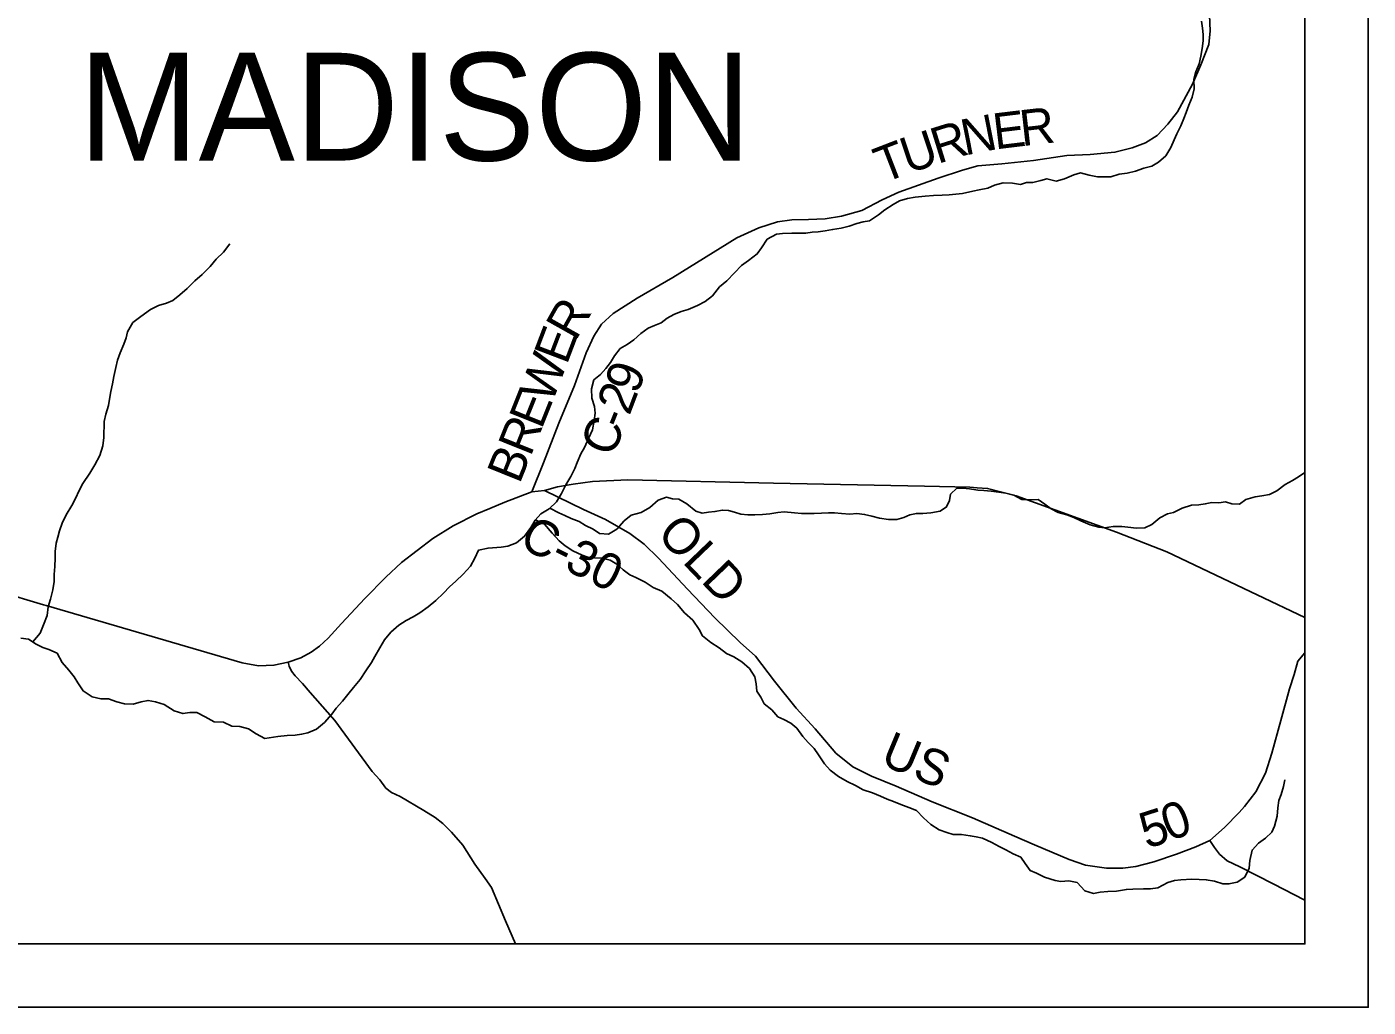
# Model space of a CAD drawing. Extents: x 0 to 34, y 0 to 22.
# Drawn here: x 28.295 to 30.417, y 14 to 15.55 of the extents above; entities that cross this region are included whole.
import ezdxf

# ---------------------------------------------------------------- set-up
doc = ezdxf.new("R2010")
doc.units = 0
for name, color, linetype in [('GM_X_County_Road', 7, 'Continuous'), ('GM_X_County_Road_Text', 7, 'Continuous'), ('GM_X_Minor_River', 7, 'Continuous'), ('GM_X_Township_Road', 7, 'Continuous'), ('GM_X_Township_Text', 7, 'Continuous'), ('GM_X_US_Route', 7, 'Continuous'), ('SH_Data', 7, 'Continuous')]:
    doc.layers.add(name, color=color, linetype=linetype)

msp = doc.modelspace()

# ---------------------------------------------------------------- linework, layer by layer
at = {"layer": 'GM_X_County_Road'}
for points in [[(29.0942, 14.815), (29.1127, 14.8606), (29.1368, 14.9236), (29.1618, 14.9831), (29.1801, 15.0347), (29.1922, 15.061), (29.2042, 15.08), (29.2229, 15.0971), (29.2605, 15.1211), (29.3173, 15.1536), (29.4185, 15.2164), (29.4533, 15.2326), (29.4824, 15.242), (29.5052, 15.2449), (29.5315, 15.2458), (29.5578, 15.2465), (29.584, 15.2509), (29.616, 15.2598), (29.648, 15.2766), (29.6743, 15.2889), (29.7369, 15.3107), (29.7752, 15.3234), (29.7993, 15.3307), (29.8373, 15.3338), (29.8873, 15.3389), (29.9402, 15.3468), (29.9772, 15.3484), (30.0161, 15.3519), (30.0437, 15.3589), (30.0646, 15.3668), (30.0829, 15.3785), (30.0997, 15.3962), (30.1152, 15.4161), (30.139, 15.4598), (30.1523, 15.4899), (30.1649, 15.5225), (30.1668, 15.5437), (30.1656, 15.5687)], [(29.1143, 14.8169), (29.1757, 14.7872), (29.2106, 14.771), (29.2491, 14.7492), (29.2719, 14.7321), (29.2944, 14.7099), (29.3403, 14.6612), (29.3834, 14.6156), (29.4234, 14.5765), (29.4479, 14.5549), (29.478, 14.5153), (29.5119, 14.4726), (29.5422, 14.4402), (29.5746, 14.4019), (29.6018, 14.3798), (29.6312, 14.3652), (29.6705, 14.3494), (29.7271, 14.3247), (29.7908, 14.2992), (29.8572, 14.2702), (29.8889, 14.2566), (29.944, 14.2335), (29.9699, 14.2243), (30.0028, 14.2199), (30.0285, 14.2199), (30.0491, 14.2224), (30.0779, 14.2297), (30.1133, 14.2421), (30.1443, 14.2538), (30.1664, 14.2635)], [(30.1664, 14.2635), (30.1893, 14.2842), (30.2124, 14.3079), (30.2209, 14.3174), (30.239, 14.3405), (30.2545, 14.37), (30.2643, 14.4016), (30.2786, 14.4532), (30.2925, 14.5032), (30.2995, 14.5263), (30.3052, 14.5471), (30.3167, 14.5601)], [(30.3167, 14.1692), (30.2666, 14.1951), (30.2138, 14.2219), (30.1936, 14.2315), (30.1817, 14.2419), (30.1734, 14.2523), (30.1664, 14.2635)]]:
    msp.add_lwpolyline(points, dxfattribs=at)
at = {"layer": 'GM_X_Minor_River'}
for points in [[(30.1409, 15.4671), (30.1439, 15.479), (30.1495, 15.4915), (30.1522, 15.504), (30.1541, 15.5158), (30.1556, 15.5283), (30.1555, 15.5382), (30.1548, 15.548), (30.1532, 15.559)], [(29.6656, 15.2691), (29.6754, 15.2752), (29.6883, 15.279), (29.7004, 15.2809), (29.716, 15.2825), (29.7292, 15.2836), (29.7432, 15.284), (29.7542, 15.2844), (29.7648, 15.2856), (29.775, 15.2867), (29.7913, 15.2902), (29.8016, 15.2925), (29.8152, 15.2951), (29.8258, 15.3001), (29.8394, 15.3035), (29.8542, 15.3028), (29.8667, 15.3009), (29.8765, 15.3039), (29.8864, 15.3043), (29.8989, 15.3074), (29.9087, 15.3101), (29.9231, 15.3063), (29.9364, 15.3101), (29.9511, 15.3162), (29.9617, 15.3192), (29.9754, 15.3158), (29.9887, 15.3132), (29.9993, 15.3128), (30.0095, 15.3132), (30.0227, 15.3174), (30.0356, 15.319), (30.0485, 15.322), (30.0617, 15.327), (30.0746, 15.33), (30.0852, 15.3361), (30.0969, 15.3463), (30.1045, 15.3596), (30.1098, 15.3714), (30.1143, 15.3809), (30.1204, 15.3938), (30.1253, 15.4055), (30.1287, 15.415), (30.1332, 15.4264), (30.1385, 15.4389), (30.1415, 15.4522), (30.1409, 15.4671)], [(28.6717, 14.4251), (28.6924, 14.4282), (28.7071, 14.4297), (28.72, 14.4301), (28.7299, 14.4316), (28.7401, 14.4336), (28.7533, 14.4396), (28.7662, 14.4503), (28.7776, 14.4632), (28.7847, 14.4727), (28.7946, 14.4841), (28.8029, 14.4947), (28.812, 14.5057), (28.8226, 14.5182), (28.8316, 14.5319), (28.8403, 14.5448), (28.846, 14.5547), (28.8536, 14.568), (28.8611, 14.5809), (28.8713, 14.593), (28.8838, 14.604), (28.8956, 14.6112), (28.9062, 14.6173), (28.9171, 14.6234), (28.93, 14.6333), (28.9421, 14.6432), (28.9542, 14.6546), (28.9637, 14.6648), (28.9739, 14.6736), (28.9856, 14.6846), (28.9973, 14.6975), (29.0041, 14.71), (29.0098, 14.7229), (29.025, 14.726), (29.0454, 14.7275), (29.056, 14.729), (29.07, 14.7344), (29.0825, 14.7446), (29.0927, 14.7583), (29.0995, 14.77), (29.1082, 14.7803), (29.1215, 14.7879), (29.1332, 14.7993), (29.1411, 14.8122), (29.1479, 14.8262), (29.1559, 14.8391), (29.1619, 14.8517), (29.1657, 14.8615), (29.1717, 14.8748), (29.1774, 14.8851), (29.1838, 14.8991), (29.1899, 14.9128), (29.1929, 14.9276), (29.194, 14.9393), (29.1932, 14.9499), (29.1891, 14.9632), (29.1887, 14.9776), (29.1921, 14.992), (29.2027, 15.0004), (29.211, 15.0099), (29.2185, 15.0194), (29.225, 15.03), (29.234, 15.0414), (29.2446, 15.0478), (29.2556, 15.0554), (29.2662, 15.0653), (29.2783, 15.0737), (29.2882, 15.0782), (29.2984, 15.0824), (29.3082, 15.0893), (29.3185, 15.0954), (29.3302, 15.0999), (29.3415, 15.1033), (29.3559, 15.1098), (29.3684, 15.1159), (29.3798, 15.125), (29.3911, 15.1391), (29.4025, 15.1486), (29.4146, 15.1615), (29.4259, 15.1729), (29.4365, 15.1808), (29.4505, 15.1911), (29.4573, 15.2006), (29.4664, 15.2143), (29.4808, 15.2222), (29.4906, 15.2234), (29.505, 15.2242), (29.5168, 15.2238), (29.5274, 15.2238), (29.5372, 15.2254), (29.5471, 15.2261), (29.5577, 15.2277), (29.5698, 15.2296), (29.5831, 15.2319), (29.5959, 15.2353), (29.6081, 15.2391), (29.6179, 15.2418), (29.6281, 15.2437), (29.6421, 15.2532), (29.6523, 15.2608), (29.6656, 15.2691)], [(28.3051, 14.5775), (28.3164, 14.5912), (28.3218, 14.6048), (28.3275, 14.6196), (28.329, 14.6329), (28.3328, 14.6454), (28.3366, 14.6598), (28.3389, 14.673), (28.3389, 14.684), (28.3397, 14.6969), (28.3401, 14.7102), (28.3405, 14.7204), (28.342, 14.7337), (28.3443, 14.7431), (28.347, 14.7534), (28.3515, 14.7655), (28.3576, 14.7787), (28.3667, 14.7935), (28.3724, 14.8045), (28.3781, 14.817), (28.3841, 14.828), (28.3951, 14.8446), (28.4031, 14.8575), (28.4111, 14.8723), (28.4156, 14.8878), (28.4175, 14.9007), (28.4176, 14.9264), (28.4206, 14.9378), (28.4248, 14.9514), (28.426, 14.9617), (28.4283, 14.9738), (28.4309, 14.9855), (28.4328, 14.9973), (28.4363, 15.0113), (28.4386, 15.0234), (28.4431, 15.0348), (28.4488, 15.0484), (28.4526, 15.0587), (28.4545, 15.0681), (28.4632, 15.0825), (28.4757, 15.0923), (28.4909, 15.1033), (28.5037, 15.1094), (28.5166, 15.1131), (28.5264, 15.1173), (28.5374, 15.1267), (28.5488, 15.1366), (28.5613, 15.1487), (28.5727, 15.1585), (28.5852, 15.1714), (28.595, 15.1831), (28.6064, 15.1937), (28.6166, 15.207)], [(30.2722, 14.8164), (30.2855, 14.8267), (30.2968, 14.8331), (30.3067, 14.8385), (30.3167, 14.8453)], [(29.1225, 14.7889), (29.1366, 14.7819), (29.1461, 14.7773), (29.1563, 14.7728), (29.1689, 14.7679), (29.1787, 14.7618), (29.1912, 14.7558), (29.2011, 14.749), (29.2151, 14.7482), (29.2283, 14.7558), (29.2401, 14.7691), (29.251, 14.7782), (29.2669, 14.782), (29.2809, 14.7904), (29.2938, 14.8018), (29.3071, 14.8064), (29.3165, 14.8041), (29.3264, 14.8034), (29.3393, 14.7962), (29.3533, 14.7844), (29.3635, 14.7814), (29.3734, 14.7826), (29.3836, 14.7837), (29.3954, 14.786), (29.4052, 14.7856), (29.4147, 14.783), (29.4245, 14.7796), (29.4359, 14.7785), (29.4469, 14.7785), (29.459, 14.7789), (29.4704, 14.7804), (29.4832, 14.782), (29.4931, 14.7835), (29.5094, 14.7816), (29.5207, 14.7805), (29.531, 14.7809), (29.5408, 14.7809), (29.5522, 14.7813), (29.5632, 14.7817), (29.5726, 14.7817), (29.5836, 14.7806), (29.5969, 14.7798), (29.6082, 14.7806), (29.6204, 14.7791), (29.6317, 14.7765), (29.6439, 14.7735), (29.6583, 14.7712), (29.6715, 14.7712), (29.6821, 14.7743), (29.692, 14.7785), (29.7022, 14.7807), (29.7124, 14.7808), (29.7249, 14.7815), (29.7397, 14.7846), (29.7499, 14.791), (29.7548, 14.8013), (29.7563, 14.8115), (29.7661, 14.8207), (29.7756, 14.8207), (29.7862, 14.8195), (29.7995, 14.8177), (29.809, 14.8169), (29.8203, 14.8158), (29.8328, 14.8143), (29.8438, 14.8128), (29.8563, 14.8098), (29.8688, 14.803), (29.8813, 14.8022), (29.8946, 14.8026), (29.9056, 14.7954), (29.9154, 14.7879), (29.9264, 14.7822), (29.9401, 14.7784), (29.9511, 14.7743), (29.9624, 14.769), (29.9768, 14.7629), (29.9905, 14.7588), (29.9999, 14.758), (30.0136, 14.7599), (30.0272, 14.76), (30.0367, 14.7592), (30.0503, 14.7573), (30.0636, 14.7581), (30.0746, 14.7634), (30.0874, 14.7737), (30.0992, 14.7802), (30.109, 14.7824), (30.1223, 14.7889), (30.1374, 14.7939), (30.1488, 14.7946), (30.159, 14.7958), (30.1696, 14.7981), (30.1806, 14.7977), (30.1908, 14.7992), (30.201, 14.7962), (30.2132, 14.7955), (30.2234, 14.8027), (30.2378, 14.8069), (30.2484, 14.8084), (30.2605, 14.8107), (30.2722, 14.8164)], [(29.0999, 14.7705), (29.1143, 14.764), (29.1264, 14.7496), (29.1374, 14.7375), (29.1469, 14.7295), (29.1591, 14.7216), (29.1735, 14.7148), (29.1829, 14.7114), (29.1932, 14.7103), (29.2049, 14.7099), (29.2182, 14.7069), (29.2284, 14.7005), (29.2383, 14.6914), (29.2493, 14.6838), (29.2587, 14.6796), (29.2731, 14.6721), (29.286, 14.6637), (29.2997, 14.6577), (29.3145, 14.6456), (29.3243, 14.6369), (29.3357, 14.6236), (29.3486, 14.6119), (29.3585, 14.5971), (29.3642, 14.5872), (29.3774, 14.5766), (29.3903, 14.5683), (29.4017, 14.5592), (29.4134, 14.5539), (29.4263, 14.546), (29.4385, 14.5354), (29.4468, 14.5225), (29.4487, 14.5111), (29.4499, 14.4998), (29.4563, 14.4903), (29.4613, 14.4797), (29.4734, 14.4702), (29.4833, 14.4592), (29.4927, 14.4547), (29.5037, 14.449), (29.5132, 14.4411), (29.5227, 14.4282), (29.531, 14.4183), (29.5405, 14.4089), (29.5473, 14.399), (29.5568, 14.385), (29.5659, 14.3748), (29.5788, 14.3649), (29.5925, 14.357), (29.6057, 14.3506), (29.6179, 14.3438), (29.6326, 14.3388), (29.6452, 14.3339), (29.6558, 14.329), (29.666, 14.3252), (29.6777, 14.3207), (29.6903, 14.3158), (29.7024, 14.3109), (29.7134, 14.2995), (29.7248, 14.2889), (29.738, 14.2806), (29.7502, 14.2761), (29.7604, 14.273), (29.7736, 14.2731), (29.7873, 14.2712), (29.7968, 14.2693), (29.8066, 14.267), (29.8214, 14.2602), (29.8331, 14.2542), (29.8438, 14.2489), (29.8555, 14.2425), (29.8673, 14.2372), (29.8741, 14.2273), (29.8821, 14.2159), (29.8919, 14.2118), (29.9048, 14.2054), (29.9215, 14.2001), (29.9309, 14.1989), (29.9434, 14.1997), (29.9563, 14.1971), (29.9685, 14.1842), (29.9821, 14.1797), (29.9931, 14.1816), (30.0052, 14.1827), (30.0188, 14.1835), (30.0344, 14.1862), (30.0446, 14.1866), (30.0613, 14.187), (30.0722, 14.187), (30.084, 14.1885), (30.0999, 14.1973), (30.1105, 14.2003), (30.1203, 14.2015), (30.1378, 14.2026), (30.1495, 14.2019), (30.1605, 14.2015), (30.1737, 14.1993), (30.187, 14.1948), (30.1965, 14.1948), (30.2094, 14.1978), (30.2215, 14.2054), (30.2283, 14.2198)], [(28.2862, 14.5833), (28.2979, 14.5821), (28.3104, 14.5742), (28.3206, 14.5688), (28.3304, 14.5654), (28.3432, 14.5597), (28.3512, 14.5453), (28.3617, 14.5328), (28.3704, 14.5225), (28.3761, 14.5131), (28.3844, 14.5002), (28.3987, 14.491)], [(28.3987, 14.491), (28.4123, 14.4876), (28.4248, 14.4876), (28.4377, 14.483), (28.4501, 14.4796), (28.4634, 14.4792), (28.4762, 14.483), (28.4872, 14.4852), (28.4989, 14.4829), (28.5129, 14.4784), (28.5284, 14.4685), (28.5424, 14.4643), (28.5534, 14.4662), (28.5643, 14.4662), (28.5776, 14.4593), (28.5919, 14.4513), (28.6063, 14.4506), (28.6199, 14.4445), (28.6324, 14.4441), (28.646, 14.4403), (28.6581, 14.4323), (28.6717, 14.4251)], [(30.2283, 14.2198), (30.2294, 14.232), (30.2332, 14.2483), (30.243, 14.2593), (30.2543, 14.2673), (30.2642, 14.2768), (30.2687, 14.2863), (30.2725, 14.3018), (30.274, 14.3151), (30.2755, 14.3268), (30.2789, 14.3363), (30.2827, 14.3492), (30.2849, 14.3595)]]:
    msp.add_lwpolyline(points, dxfattribs=at)
at = {"layer": 'GM_X_Township_Road'}
msp.add_lwpolyline([(29.068, 14.1), (29.0526, 14.1367), (29.0304, 14.1895), (29.0203, 14.2035), (29.0038, 14.2259), (28.9848, 14.256), (28.9671, 14.2769), (28.9532, 14.2902), (28.9411, 14.2997), (28.9234, 14.3111), (28.8861, 14.3332), (28.8721, 14.3396), (28.8633, 14.3462), (28.8535, 14.3595), (28.8417, 14.3725), (28.7826, 14.4535), (28.7712, 14.4665), (28.7436, 14.4975), (28.7313, 14.5118), (28.7196, 14.5241), (28.7142, 14.5311), (28.7104, 14.539), (28.7088, 14.5456)], dxfattribs=at)
at = {"layer": 'GM_X_US_Route'}
for points in [[(28.322, 14.6364), (28.3259, 14.6353), (28.6358, 14.5445), (28.662, 14.5399), (28.6863, 14.5406), (28.7088, 14.5456), (28.7287, 14.5526), (28.7452, 14.5615), (28.7582, 14.571), (28.7718, 14.5836), (28.793, 14.6067), (28.83, 14.646), (28.863, 14.6798), (28.888, 14.7033), (28.9373, 14.7413), (28.9699, 14.7609), (29.007, 14.7802), (29.0276, 14.7884), (29.0513, 14.7986), (29.0942, 14.815), (29.1143, 14.8169), (29.1349, 14.8229), (29.1596, 14.8271), (29.19, 14.8315), (29.246, 14.8337), (29.4764, 14.8286), (29.7148, 14.8239), (29.7866, 14.8223), (29.7984, 14.8214), (29.8149, 14.8204), (29.8601, 14.8087), (30.0187, 14.7511), (30.0985, 14.7202), (30.2412, 14.6523), (30.3167, 14.6163)], [(28.0654, 14.71), (28.1194, 14.6956), (28.251, 14.6571), (28.322, 14.6364)]]:
    msp.add_lwpolyline(points, dxfattribs=at)
at = {"layer": 'SH_Data'}
for points in [[(23.4167, 21), (30.4167, 21), (30.4167, 14), (23.4167, 14)], [(23.5167, 20.9), (30.3167, 20.9), (30.3167, 14.1), (23.5167, 14.1)]]:
    msp.add_lwpolyline(points, close=True, dxfattribs=at)

# ---------------------------------------------------------------- texts
at = {"layer": 'GM_X_County_Road_Text'}
for s, height, rotation, p in [('R', 0.0568, 6.5402, (29.8689, 15.3614)), ('N', 0.0568, 11.2221, (29.7789, 15.3467)), ('E', 0.0568, 6.9124, (29.8268, 15.3563)), ('U', 0.0568, 18.5041, (29.6887, 15.3175)), ('R', 0.0568, 17.3019, (29.7358, 15.3332)), ('T', 0.0568, 21.1178, (29.6497, 15.3024)), ('R', 0.0568, 60.7092, (29.1634, 15.0522)), ('E', 0.0568, 69.1729, (29.1492, 15.0145)), ('W', 0.0568, 68.9712, (29.1255, 14.9528)), ('9', 0.0568, 69.9774, (29.2611, 14.9677)), ('E', 0.0568, 68.1071, (29.1093, 14.9125)), ('2', 0.0568, 69.1721, (29.2483, 14.9342)), ('-', 0.0568, 68.2213, (29.2393, 14.9116)), ('R', 0.0568, 68.1026, (29.0919, 14.8692)), ('C', 0.0568, 68.0217, (29.2218, 14.8681)), ('B', 0.0568, 68.0986, (29.0745, 14.8259)), ('C-30', 0.05682, 333.4407, (29.0716, 14.729)), ('OLD', 0.05682, 313.8399, (29.2898, 14.7463)), ('US', 0.05682, 337.3781, (29.643, 14.3849)), ('0', 0.0568, 20.6192, (30.1024, 14.2618)), ('5', 0.0568, 17.7619, (30.0662, 14.2501))]:
    msp.add_text(s, height=height, rotation=rotation, dxfattribs=at).set_placement(p)
at = {"layer": 'GM_X_Township_Text'}
msp.add_text('MADISON', height=0.17045, rotation=0, dxfattribs=at).set_placement((28.3774, 15.3388))

doc.saveas('drawing.dxf')
